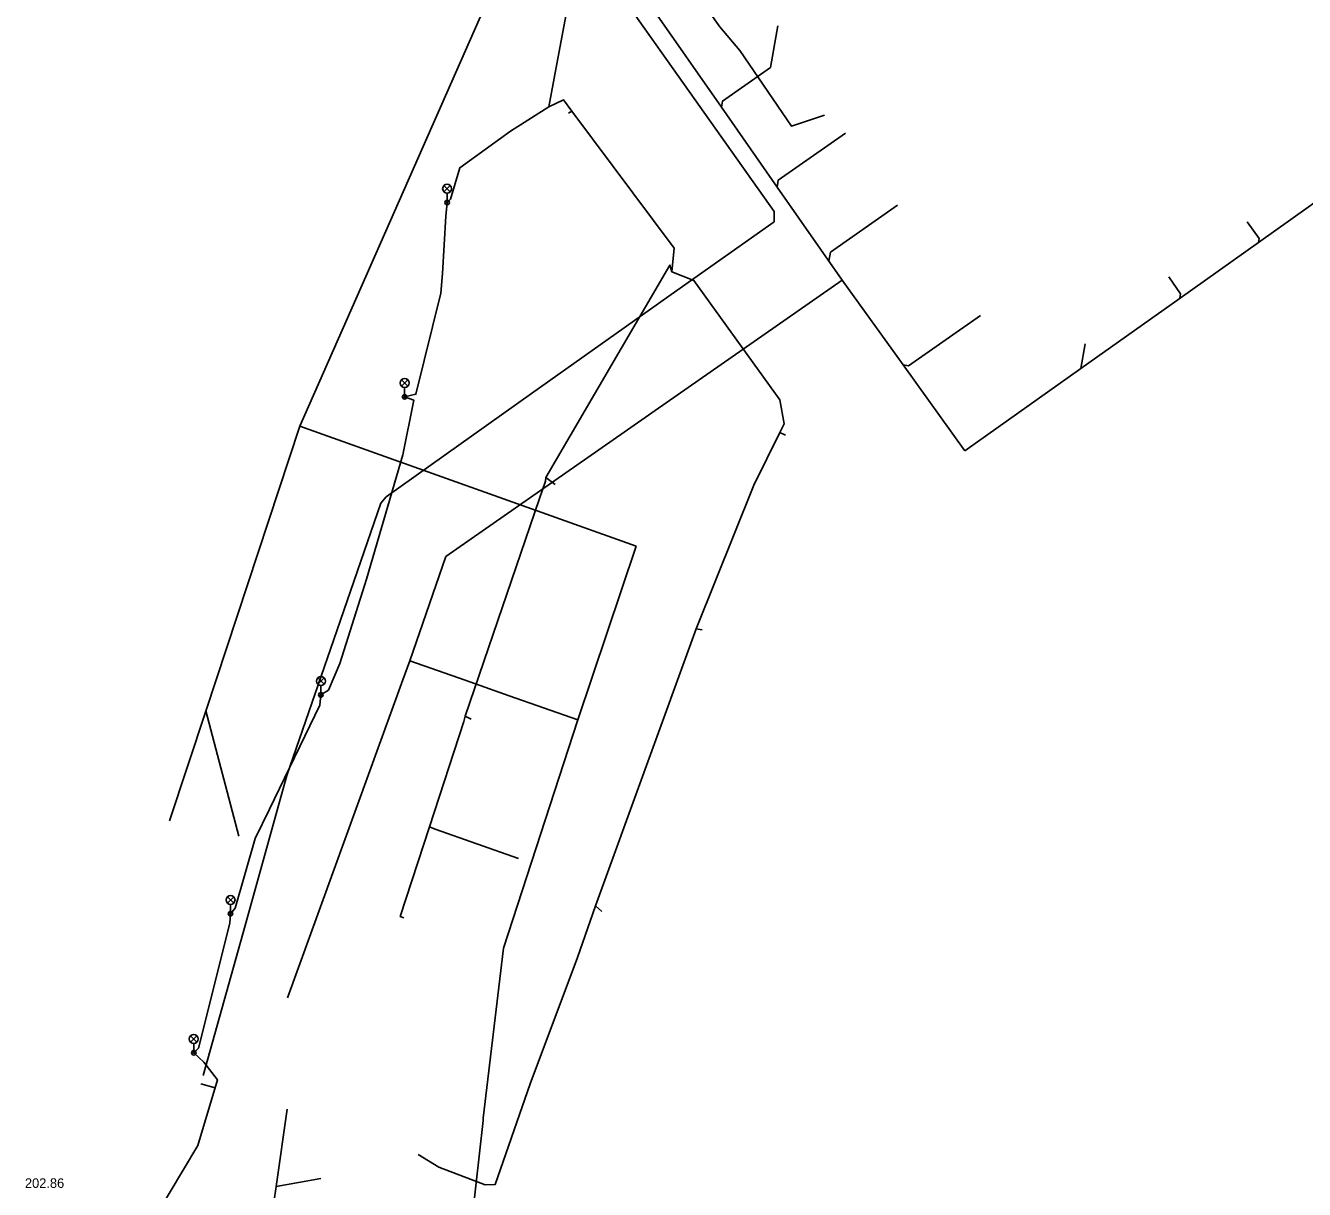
# Model space of a CAD drawing. Extents: x -596228 to -595156, y -1161235 to -1159373.
# Drawn here: x -596084.5 to -595977.9, y -1160242.3 to -1160145.3 of the extents above; entities that cross this region are included whole.
import ezdxf

# ---------------------------------------------------------------- set-up
doc = ezdxf.new("R2010")
doc.units = 0
for name, color, linetype in [('Vrstva 1', 7, 'Continuous'), ('Vrstva 14', 7, 'Continuous'), ('Vrstva 33', 7, 'Continuous'), ('Vrstva 4', 7, 'Continuous'), ('Vrstva 5', 7, 'Continuous'), ('Vrstva 55', 7, 'Continuous'), ('Vrstva 9', 7, 'Continuous')]:
    doc.layers.add(name, color=color, linetype=linetype)

msp = doc.modelspace()

# ---------------------------------------------------------------- linework, layer by layer
at = {"layer": 'Vrstva 1'}
for p, q in [((-596043.61, -1160137.85), (-596061.61, -1160178.689)), ((-596061.61, -1160178.69), (-596033.58, -1160188.7)), ((-596033.58, -1160188.7), (-596038.46, -1160203.142)), ((-596049.46, -1160189.56), (-596052.46, -1160198.24)), ((-596052.46, -1160198.24), (-596047.84, -1160199.85)), ((-596047.84, -1160199.85), (-596044.18, -1160201.15)), ((-596044.18, -1160201.15), (-596038.46, -1160203.142)), ((-596038.46, -1160203.142), (-596044.65, -1160222.16)), ((-596046.34, -1160236.52), (-596047.88, -1160250.29))]:
    msp.add_line(p, q, dxfattribs=at)
for points in [[(-596036.97, -1160137.11), (-596032.22, -1160143.916), (-596026.481, -1160152.141), (-596021.848, -1160158.78), (-596016.44, -1160166.53)], [(-595972.17, -1160156.6), (-595976.352, -1160159.563), (-595981.746, -1160163.395), (-595988.272, -1160168.027), (-595996.548, -1160173.9), (-596006.2, -1160180.75)], [(-596016.44, -1160166.53), (-596032.001, -1160177.383), (-596034.604, -1160179.198), (-596049.46, -1160189.56)], [(-596006.2, -1160180.75), (-596011.351, -1160173.597), (-596016.44, -1160166.53)], [(-596072.47, -1160211.58), (-596069.453, -1160202.444), (-596061.61, -1160178.69)], [(-596062.64, -1160226.32), (-596053.021, -1160199.813), (-596052.46, -1160198.24)], [(-596044.65, -1160222.16), (-596046.35, -1160236.32), (-596046.34, -1160236.52)]]:
    msp.add_lwpolyline(points, dxfattribs=at)
at = {"layer": 'Vrstva 14'}
for p, q in [((-596030.98, -1160148.26), (-596039.88, -1160135.71)), ((-596022.08, -1160160.81), (-596030.98, -1160148.26)), ((-596022.08, -1160161.24), (-596022.08, -1160160.81)), ((-596022.08, -1160161.67), (-596022.08, -1160161.24)), ((-596026.145, -1160164.53), (-596022.08, -1160161.67)), ((-596030.21, -1160167.39), (-596026.145, -1160164.53)), ((-596042.315, -1160175.98), (-596030.21, -1160167.39)), ((-596054.42, -1160184.57), (-596042.315, -1160175.98)), ((-596062.69, -1160207.8), (-596058.78, -1160196.46)), ((-596066.177, -1160220.291), (-596062.69, -1160207.8)), ((-596069.665, -1160232.782), (-596066.177, -1160220.291))]:
    msp.add_line(p, q, dxfattribs=at)
msp.add_lwpolyline([(-596058.78, -1160196.46), (-596054.87, -1160185.12), (-596054.42, -1160184.57)], dxfattribs=at)
at = {"layer": 'Vrstva 33'}
for p, q in [((-596049.605, -1160158.655), (-596049.075, -1160159.185)), ((-596049.605, -1160159.185), (-596049.075, -1160158.655)), ((-596049.34, -1160160.07), (-596049.34, -1160159.295)), ((-596053.145, -1160174.835), (-596052.615, -1160175.365)), ((-596053.145, -1160175.365), (-596052.615, -1160174.835)), ((-596052.88, -1160176.25), (-596052.88, -1160175.475)), ((-596060.125, -1160199.665), (-596059.595, -1160200.195)), ((-596060.125, -1160200.195), (-596059.595, -1160199.665)), ((-596059.86, -1160201.08), (-596059.86, -1160200.305)), ((-596067.655, -1160217.885), (-596067.125, -1160218.415)), ((-596067.655, -1160218.415), (-596067.125, -1160217.885)), ((-596067.39, -1160219.3), (-596067.39, -1160218.525)), ((-596070.715, -1160229.465), (-596070.185, -1160229.995)), ((-596070.715, -1160229.995), (-596070.185, -1160229.465)), ((-596070.45, -1160230.88), (-596070.45, -1160230.105))]:
    msp.add_line(p, q, dxfattribs=at)
for centre, radius in [((-596049.34, -1160158.92), 0.375), ((-596049.34, -1160160.07), 0.19), ((-596049.34, -1160160.07), 0.05), ((-596052.88, -1160175.1), 0.375), ((-596052.88, -1160176.25), 0.19), ((-596052.88, -1160176.25), 0.05), ((-596059.86, -1160199.93), 0.375), ((-596059.86, -1160201.08), 0.19), ((-596059.86, -1160201.08), 0.05), ((-596067.39, -1160218.15), 0.375), ((-596067.39, -1160219.3), 0.19), ((-596067.39, -1160219.3), 0.05), ((-596070.45, -1160229.73), 0.375), ((-596070.45, -1160230.88), 0.19), ((-596070.45, -1160230.88), 0.05)]:
    msp.add_circle(centre, radius, dxfattribs=at)
at = {"layer": 'Vrstva 5'}
for p, q in [((-596026.63, -1160145.43), (-596036.9, -1160130.77)), ((-596024.96, -1160147.42), (-596026.63, -1160145.43)), ((-596063.596, -1160242.034), (-596062.661, -1160235.576)), ((-596059.87, -1160241.358), (-596063.596, -1160242.034)), ((-596064.183, -1160246.083), (-596063.596, -1160242.034))]:
    msp.add_line(p, q, dxfattribs=at)
msp.add_lwpolyline([(-596017.9, -1160152.81), (-596020.656, -1160153.71), (-596024.96, -1160147.42)], dxfattribs=at)
at = {"layer": 'Vrstva 55'}
for p, q in [((-596038.96, -1160152.45), (-596039.22, -1160152.64)), ((-596021.63, -1160179.22), (-596021.15, -1160179.45)), ((-596041.13, -1160182.98), (-596040.35, -1160183.57)), ((-596047.83, -1160202.84), (-596041.65, -1160184.72)), ((-596036.98, -1160218.65), (-596028.6, -1160195.58)), ((-596028.6, -1160195.58), (-596028.08, -1160195.65)), ((-596047.83, -1160202.84), (-596047.33, -1160203.11)), ((-596036.98, -1160218.65), (-596036.46, -1160219.11)), ((-596068.68, -1160233.81), (-596069.87, -1160233.46))]:
    msp.add_line(p, q, dxfattribs=at)
for points in [[(-596037.948, -1160136.522), (-596040.19, -1160148.508), (-596040.86, -1160152.09), (-596044.05, -1160154.13), (-596048.28, -1160157.18), (-596049.07, -1160159.79), (-596049.34, -1160160.07), (-596049.45, -1160161.2), (-596049.72, -1160165.97), (-596049.86, -1160167.61), (-596051.94, -1160176.04), (-596052.88, -1160176.25), (-596052.11, -1160176.54), (-596053.02, -1160181.09), (-596056.05, -1160191.44), (-596058.27, -1160198.46), (-596059.22, -1160200.68), (-596059.86, -1160201.08), (-596059.96, -1160201.94), (-596064.153, -1160210.583), (-596065.35, -1160213.05), (-596067.01, -1160218.84), (-596067.39, -1160219.3), (-596067.44, -1160220.06), (-596069.614, -1160228.748), (-596070.05, -1160230.49)], [(-596040.86, -1160152.09), (-596039.64, -1160151.53), (-596038.96, -1160152.45)], [(-596030.62, -1160165.84), (-596030.42, -1160163.88), (-596038.96, -1160152.45)], [(-596041.13, -1160182.98), (-596030.78, -1160165.28), (-596030.62, -1160165.84)], [(-596021.63, -1160179.22), (-596021.27, -1160178.49), (-596021.61, -1160176.51), (-596028.78, -1160166.57), (-596030.62, -1160165.84)], [(-596028.6, -1160195.58), (-596023.78, -1160183.62), (-596021.63, -1160179.22)], [(-596041.65, -1160184.72), (-596041.15, -1160183.27), (-596041.13, -1160182.98)], [(-596050.82, -1160212.08), (-596047.95, -1160203.3), (-596047.83, -1160202.84)], [(-596052.94, -1160219.64), (-596053.25, -1160219.53), (-596050.82, -1160212.08)], [(-596050.82, -1160212.08), (-596050.34, -1160212.25), (-596043.4, -1160214.71)], [(-596051.76, -1160239.37), (-596050.03, -1160240.41), (-596046.17, -1160241.87), (-596045.34, -1160241.86), (-596042.43, -1160233.47), (-596038.48, -1160222.95), (-596036.98, -1160218.65)], [(-596070.05, -1160230.49), (-596070.45, -1160230.88), (-596069.61, -1160231.67), (-596068.48, -1160233.14), (-596070.1, -1160238.6), (-596073.7, -1160244.6), (-596075.039, -1160249.919), (-596075.5, -1160250), (-596075.38, -1160250.25), (-596078.55, -1160261.02), (-596080.15, -1160266.81), (-596080.28, -1160269.03), (-596079.58, -1160269.78), (-596079.09, -1160270.15)]]:
    msp.add_lwpolyline(points, dxfattribs=at)
at = {"layer": 'Vrstva 9'}
for p, q in [((-596011.803, -1160160.286), (-596017.403, -1160164.207)), ((-596017.536, -1160164.96), (-596017.403, -1160164.207)), ((-595996.186, -1160171.844), (-595996.549, -1160173.901)), ((-596066.71, -1160212.84), (-596069.438, -1160202.397))]:
    msp.add_line(p, q, dxfattribs=at)
for points in [[(-596021.779, -1160145.363), (-596022.387, -1160148.816), (-596026.394, -1160151.621), (-596026.481, -1160152.141)], [(-596016.148, -1160154.286), (-596021.747, -1160158.207), (-596021.848, -1160158.78)], [(-595982.671, -1160161.667), (-595981.688, -1160163.07), (-595981.746, -1160163.399)], [(-595989.213, -1160166.271), (-595988.231, -1160167.674), (-595988.296, -1160168.044)], [(-596004.895, -1160169.478), (-596010.893, -1160173.678), (-596011.351, -1160173.597)]]:
    msp.add_lwpolyline(points, dxfattribs=at)

# ---------------------------------------------------------------- texts
at = {"layer": 'Vrstva 4'}
msp.add_text('202.86', height=0.8, dxfattribs=at).set_placement((-596084.52, -1160242.139))

doc.saveas('drawing.dxf')
